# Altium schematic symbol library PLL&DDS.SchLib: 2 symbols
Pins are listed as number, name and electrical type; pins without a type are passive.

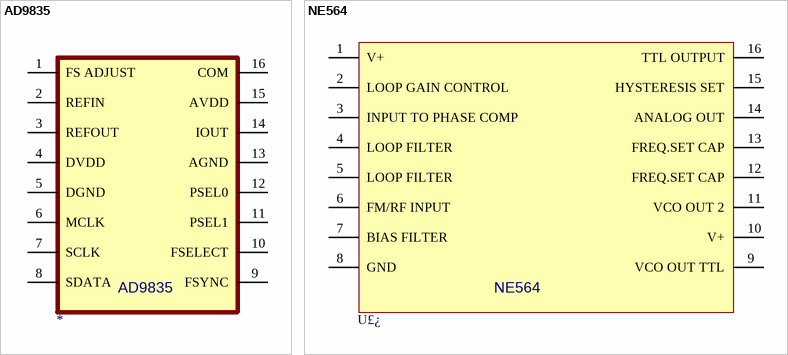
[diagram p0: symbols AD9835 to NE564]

## AD9835
designator *
50 MHz CMOS / Complete DDS
footprint TSSOP-16
pins: 1 FS ADJUST, 2 REFIN, 3 REFOUT, 4 DVDD (power), 5 DGND (power), 6 MCLK, 7 SCLK, 8 SDATA, 9 FSYNC, 10 FSELECT, 11 PSEL1, 12 PSEL0, 13 AGND (power), 14 IOUT, 15 AVDD, 16 COM

## NE564
designator U£¿
Phase-locked loop; Manufacturer: Philips; Class 1: PLL&DDS; Class 2: Phase Lock Loop
footprint DIP16
pins: 1 V+ (power), 2 LOOP GAIN CONTROL, 3 INPUT TO PHASE COMP, 4 LOOP FILTER, 5 LOOP FILTER, 6 FM/RF INPUT, 7 BIAS FILTER, 8 GND (power), 9 VCO OUT TTL, 10 V+, 11 VCO OUT 2, 12 FREQ.SET CAP, 13 FREQ.SET CAP, 14 ANALOG OUT, 15 HYSTERESIS SET, 16 TTL OUTPUT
